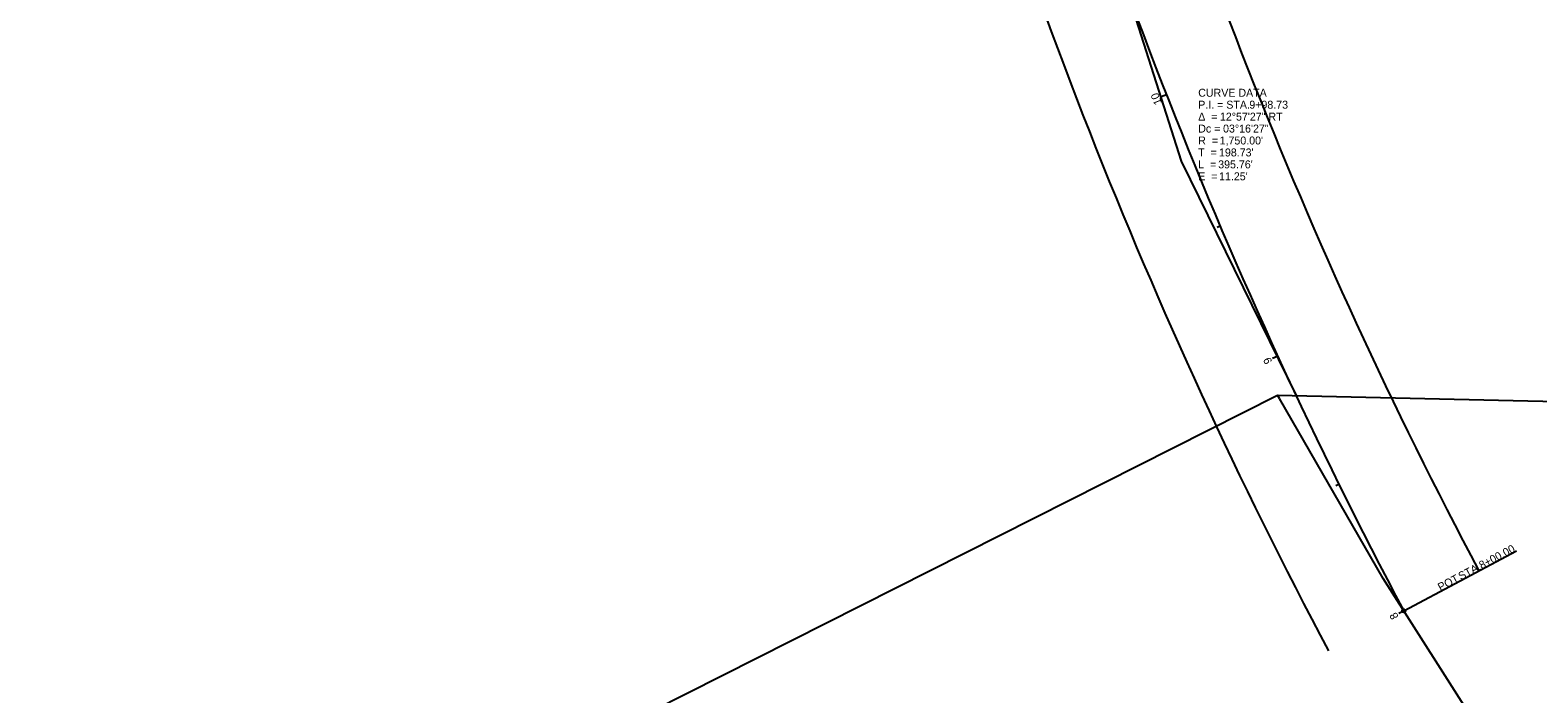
# Model space of a CAD drawing. Extents: x 2392034 to 2394211, y 184331 to 186655.
# Drawn here: x 2392516 to 2393047, y 184892 to 185125 of the extents above; entities that cross this region are included whole.
import ezdxf

# ---------------------------------------------------------------- set-up
doc = ezdxf.new("R2010")
doc.units = 0
for name, color, linetype in [('V-ROAD-SIGN', 7, 'Continuous'), ('V-SITE-MAIL', 7, 'Continuous'), ('V-SITE-MISC', 7, 'Continuous'), ('V-SITE-POST', 7, 'Continuous'), ('V-SURV-ANNO', 7, 'Continuous'), ('V-TOPO-ANNO', 7, 'Continuous')]:
    doc.layers.add(name, color=color, linetype=linetype)

msp = doc.modelspace()

# ---------------------------------------------------------------- linework, layer by layer
at = {"layer": 'V-ROAD-SIGN'}
for radius in [1720, 1780]:
    msp.add_arc((2394545.08, 185741.75), radius, 195.02013, 207.9775, dxfattribs=at)
at = {"layer": 'V-SITE-MAIL'}
msp.add_arc((2394545.08, 185741.75), 1750, 195.02013, 207.9775, dxfattribs=at)
at = {"layer": 'V-SITE-MISC'}
msp.add_line((2392999.6, 184920.78), (2393039.34, 184941.89), dxfattribs=at)
msp.add_circle((2392999.6, 184920.78), 0.6, dxfattribs=at)
at = {"layer": 'V-SURV-ANNO'}
for p, q in [((2392916.06, 185102.38), (2392914.2, 185101.65)), ((2392934.99, 185056.11), (2392933.89, 185055.64)), ((2392955.24, 185010.39), (2392953.42, 185009.55)), ((2392976.78, 184965.27), (2392975.71, 184964.74)), ((2392999.6, 184920.78), (2392997.84, 184919.85))]:
    msp.add_line(p, q, dxfattribs=at)
at = {"layer": 'V-TOPO-ANNO'}
for p, q in [((2392921.32, 185078.99), (2392843.3, 185323.45)), ((2392961.79, 184996.54), (2392921.32, 185078.99)), ((2392961.79, 184996.54), (2392921.32, 185078.99)), ((2392515.91, 184775.21), (2392955.13, 184996.69)), ((2392517.2, 184775.86), (2392955.13, 184996.69)), ((2392955.8, 184995.51), (2392955.13, 184996.69)), ((2392955.13, 184996.69), (2394052.93, 184971.91)), ((2392955.13, 184996.69), (2394052.93, 184971.91)), ((2392992.31, 184932.18), (2392955.8, 184995.51)), ((2393031.56, 184870.87), (2392992.31, 184932.18))]:
    msp.add_line(p, q, dxfattribs=at)

# ---------------------------------------------------------------- texts
at = {"layer": 'V-SITE-MISC'}
for s, p in [('8+00.00', (2393027.04, 184935.4)), (' STA. ', (2393018.81, 184931.03)), ('POT', (2393012.51, 184927.68))]:
    msp.add_text(s, height=2.8, rotation=27.9775, dxfattribs=at).set_placement(p)
at = {"layer": 'V-SITE-POST'}
for s, p in [('CURVE DATA', (2392927.24, 185101.7)), ('Δ  = ', (2392927.24, 185093.3)), ('P.I. = STA. ', (2392927.24, 185097.5)), ('12°57\'27" RT', (2392934.88, 185093.3)), ('9+98.73', (2392945.23, 185097.5)), ('Dc = ', (2392927.24, 185089.1)), ('03°16\'27"', (2392935.98, 185089.1)), ('R  = ', (2392927.24, 185084.9)), ("1,750.00'", (2392934.77, 185084.9)), ('T  = ', (2392927.24, 185080.7)), ("198.73'", (2392934.56, 185080.7)), ('L  = ', (2392927.24, 185076.5)), ('E  = ', (2392927.24, 185072.3)), ("395.76'", (2392934.27, 185076.5)), ("11.25'", (2392934.58, 185072.3))]:
    msp.add_text(s, height=2.8, dxfattribs=at).set_placement(p)
at = {"layer": 'V-SURV-ANNO'}
for s, rotation, p in [('10', 111.4294, (2392914.52, 185099.47)), ('9', 114.7035, (2392953.38, 185008.44)), ('8', 117.9775, (2392997.87, 184918.71))]:
    msp.add_text(s, height=2.8, rotation=rotation, dxfattribs=at).set_placement(p)

doc.saveas('drawing.dxf')
